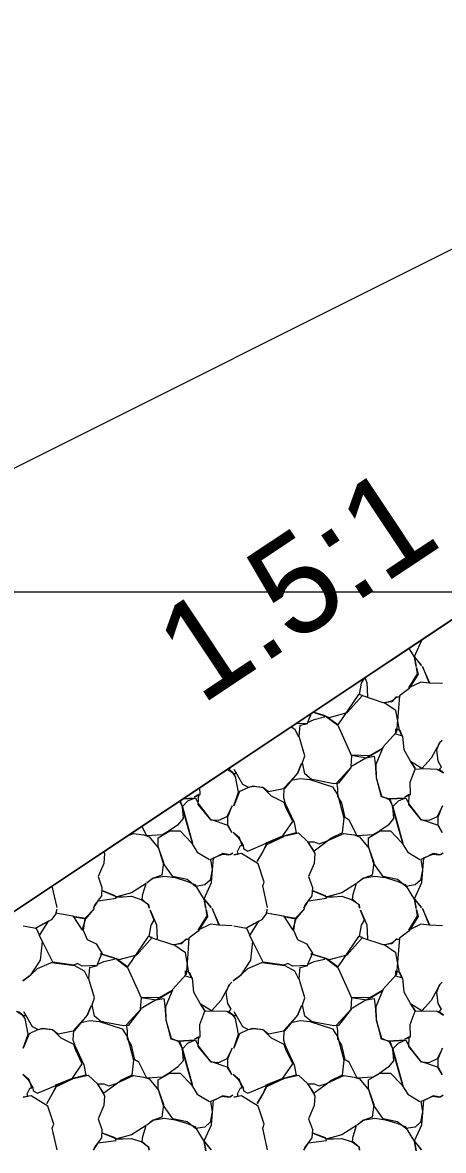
# Model space of a CAD drawing. Extents: x -26 to 2998798, y -429 to 819149.
# Drawn here: x 254.02 to 258.3, y 2527.31 to 2538.79 of the extents above; entities that cross this region are included whole.
import ezdxf

# ---------------------------------------------------------------- set-up
doc = ezdxf.new("R2010")
doc.units = 0
for name, color, linetype in [('DESIGN - EARTHWORK - Shapes', 7, 'Continuous'), ('DESIGN - PROFILE - Patterning', 7, 'Continuous'), ('DESIGN - SCRATCH - User 3', 7, 'Continuous'), ('DESIGN - SCRATCH - User 4', 7, 'Continuous'), ('DESIGN - SHEET - Linework', 7, 'Continuous'), ('DESIGN - TYPICAL - Finished Grade and Subgrade', 7, 'Continuous'), ('DESIGN - TYPICAL - Finished Grade Slopes Text', 7, 'Continuous')]:
    doc.layers.add(name, color=color, linetype=linetype)

msp = doc.modelspace()

# ---------------------------------------------------------------- linework, layer by layer
at = {"layer": 'DESIGN - EARTHWORK - Shapes'}
msp.add_lwpolyline([(309, 2547.734), (300, 2547.914), (299.208, 2547.909), (289, 2547.848), (281.017, 2547.801), (225.777, 2510.974)], dxfattribs=at)
at = {"layer": 'DESIGN - PROFILE - Patterning'}
for p, q in [((281.017, 2547.801), (225.777, 2510.974)), ((254.374, 2529.786), (254.324, 2530.005))]:
    msp.add_line(p, q, dxfattribs=at)
for points in [[(257.952, 2532.424), (258.009, 2532.331), (258.024, 2532.241), (258.009, 2532.336), (258.079, 2532.251), (258.009, 2532.341), (258.084, 2532.506), (258.084, 2532.512)], [(258.294, 2532.066), (258.164, 2532.071), (258.089, 2532.241), (258.159, 2532.071), (258.074, 2532.081), (257.949, 2532.021), (258.039, 2532.166), (258.029, 2532.231), (258.044, 2532.161), (257.949, 2532.011), (257.854, 2531.941), (257.839, 2531.731), (257.824, 2531.571), (257.689, 2531.421), (257.614, 2531.241), (257.619, 2531.106), (257.674, 2530.921), (257.749, 2530.886), (257.789, 2530.811), (257.889, 2530.441), (257.784, 2530.811), (257.844, 2530.871), (257.909, 2530.901), (257.744, 2530.891), (257.919, 2530.901), (257.959, 2530.831), (258.069, 2530.686), (258.249, 2530.626), (258.289, 2530.551), (258.249, 2530.621), (258.249, 2530.711), (258.294, 2530.821), (258.239, 2530.711), (258.154, 2530.671), (258.079, 2530.676), (257.949, 2530.836), (257.954, 2530.936), (257.909, 2530.911), (257.969, 2530.936), (257.964, 2531.061), (258.014, 2531.196), (258.104, 2531.201), (258.239, 2531.196), (258.304, 2531.156), (258.259, 2531.191), (258.284, 2531.216), (258.249, 2531.276), (258.234, 2531.391), (258.264, 2531.466), (258.289, 2531.491), (258.269, 2531.471), (258.219, 2531.381), (258.179, 2531.306), (258.084, 2531.201), (257.969, 2531.271), (258.014, 2531.201), (257.969, 2531.276), (257.904, 2531.391), (257.889, 2531.531), (257.819, 2531.551), (257.819, 2531.606), (257.859, 2531.591), (257.884, 2531.531), (257.854, 2531.591), (257.819, 2531.791), (257.699, 2531.871), (257.779, 2531.891), (257.829, 2531.931), (257.854, 2531.926), (257.819, 2531.926), (257.779, 2531.881), (257.689, 2531.871), (257.484, 2531.941), (257.449, 2531.956), (257.469, 2532.071), (257.499, 2532.121), (257.499, 2532.122)], [(257.503, 2532.124), (257.524, 2532.076), (257.529, 2531.931)], [(256.977, 2531.774), (257.144, 2531.721), (257.324, 2531.771), (257.479, 2531.946), (257.439, 2531.956), (257.229, 2531.646), (257.109, 2531.731), (257.229, 2531.641), (257.329, 2531.416), (257.369, 2531.331), (257.359, 2531.221), (257.514, 2531.311), (257.569, 2531.336), (257.684, 2531.406), (257.554, 2531.331), (257.369, 2531.336), (257.519, 2531.311), (257.599, 2531.326), (257.609, 2531.251), (257.619, 2531.111), (257.669, 2530.916), (257.759, 2530.891), (257.784, 2530.816), (257.794, 2530.691), (257.739, 2530.626), (257.654, 2530.566), (257.584, 2530.526), (257.424, 2530.516), (257.344, 2530.676), (257.304, 2530.701), (257.269, 2530.851), (257.229, 2530.916), (257.229, 2531.001), (257.219, 2531.056), (257.364, 2531.216), (257.234, 2531.051), (257.189, 2531.046), (257.004, 2531.081), (256.959, 2531.091), (256.894, 2531.146), (256.869, 2531.261), (256.894, 2531.331), (256.834, 2531.526), (256.844, 2531.641), (256.924, 2531.661), (256.802, 2531.657)], [(256.958, 2531.761), (256.919, 2531.671), (256.989, 2531.701), (257.094, 2531.726), (257.099, 2531.736), (256.977, 2531.774)], [(256.754, 2531.625), (256.789, 2531.606), (256.829, 2531.526)], [(256.514, 2529.786), (256.464, 2530.006), (256.479, 2530.046), (256.419, 2530.231), (256.249, 2530.336), (256.169, 2530.321), (256.214, 2530.331), (256.209, 2530.356), (256.239, 2530.416), (256.254, 2530.416), (256.229, 2530.496), (256.164, 2530.551), (256.219, 2530.496), (256.264, 2530.416), (256.269, 2530.386), (256.314, 2530.361), (256.499, 2530.441), (256.674, 2530.506), (256.504, 2530.426), (256.464, 2530.356), (256.409, 2530.256), (256.464, 2530.351), (256.499, 2530.426), (256.499, 2530.446), (256.669, 2530.516), (256.769, 2530.661), (256.699, 2530.806), (256.684, 2530.856), (256.554, 2530.921), (256.514, 2530.961), (256.469, 2531.006), (256.364, 2531.021), (256.314, 2531.006), (256.229, 2530.966), (256.169, 2530.821), (256.219, 2530.961), (256.189, 2531.121), (256.164, 2531.151), (256.194, 2531.151), (256.174, 2531.191), (256.259, 2531.041), (256.319, 2531.011), (256.369, 2531.021), (256.464, 2531.011), (256.524, 2530.966), (256.694, 2531.001), (256.819, 2531.151), (256.859, 2531.251), (256.819, 2531.151), (256.739, 2531.066), (256.679, 2531.001), (256.674, 2530.906), (256.694, 2530.846), (256.784, 2530.651), (256.804, 2530.546), (256.674, 2530.511), (256.829, 2530.546), (256.924, 2530.456), (256.994, 2530.336), (256.989, 2530.236), (256.929, 2530.101), (256.969, 2529.991), (256.964, 2529.906), (256.894, 2529.811), (256.884, 2529.781), (256.929, 2529.856), (257.114, 2529.881), (257.104, 2529.906), (256.974, 2529.956), (257.119, 2529.896), (257.184, 2529.896), (257.269, 2529.901), (257.374, 2529.866), (257.444, 2529.816), (257.449, 2529.781), (257.444, 2529.811), (257.379, 2529.871), (257.384, 2529.921), (257.419, 2530.031), (257.269, 2529.936), (257.119, 2529.896)], [(256.105, 2531.192), (256.164, 2531.156), (256.119, 2531.191), (256.144, 2531.216), (256.143, 2531.218)], [(255.658, 2530.894), (255.779, 2530.901), (255.819, 2530.831), (255.929, 2530.686), (256.109, 2530.626), (256.149, 2530.551), (256.109, 2530.621), (256.109, 2530.711), (256.154, 2530.821), (256.099, 2530.711), (256.014, 2530.671), (255.939, 2530.676), (255.809, 2530.836), (255.814, 2530.936), (255.769, 2530.911), (255.829, 2530.936), (255.826, 2531.007)], [(256.754, 2531.081), (256.844, 2531.101), (256.944, 2531.091), (257.174, 2531.016), (257.229, 2530.931), (257.289, 2530.696), (257.274, 2530.546), (257.159, 2530.491), (257.124, 2530.461), (256.989, 2530.361), (256.924, 2530.456), (256.989, 2530.456), (257.039, 2530.436), (257.114, 2530.461), (257.289, 2530.541), (257.394, 2530.526), (257.449, 2530.506), (257.544, 2530.391), (257.594, 2530.246), (257.579, 2530.116), (257.494, 2530.086), (257.424, 2530.036), (257.484, 2530.086), (257.604, 2530.106), (257.714, 2530.091), (257.829, 2530.056), (257.914, 2530.021), (258.009, 2529.866), (258.024, 2529.776), (258.009, 2529.871), (258.079, 2529.786), (258.009, 2529.876), (258.084, 2530.041), (258.104, 2530.291), (258.194, 2530.331), (258.259, 2530.321), (258.299, 2530.341), (258.274, 2530.321), (258.199, 2530.336), (258.114, 2530.291), (258.074, 2530.276), (258.089, 2530.171), (258.069, 2530.066), (258.014, 2530.016), (257.919, 2530.001), (257.834, 2530.071), (257.689, 2530.101), (257.594, 2530.236), (257.539, 2530.406), (257.539, 2530.496), (257.659, 2530.566), (257.764, 2530.566), (257.879, 2530.446), (257.939, 2530.351), (258.064, 2530.276)], [(255.618, 2530.868), (255.649, 2530.811), (255.749, 2530.441), (255.644, 2530.811), (255.704, 2530.871), (255.769, 2530.901), (255.658, 2530.894)], [(255.625, 2530.873), (255.644, 2530.816), (255.654, 2530.691), (255.599, 2530.626), (255.514, 2530.566), (255.444, 2530.526), (255.284, 2530.516), (255.235, 2530.613)], [(255.082, 2530.511), (255.149, 2530.541), (255.254, 2530.526), (255.309, 2530.506), (255.404, 2530.391), (255.454, 2530.246), (255.439, 2530.116), (255.354, 2530.086), (255.284, 2530.036), (255.344, 2530.086), (255.464, 2530.106), (255.574, 2530.091), (255.689, 2530.056), (255.774, 2530.021), (255.869, 2529.866), (255.884, 2529.776), (255.869, 2529.871), (255.939, 2529.786), (255.869, 2529.876), (255.944, 2530.041), (255.964, 2530.291), (256.054, 2530.331), (256.119, 2530.321), (256.159, 2530.341), (256.134, 2530.321), (256.059, 2530.336), (255.974, 2530.291), (255.934, 2530.276), (255.949, 2530.171), (255.929, 2530.066), (255.874, 2530.016), (255.779, 2530.001), (255.694, 2530.071), (255.549, 2530.101), (255.454, 2530.236), (255.399, 2530.406), (255.399, 2530.496), (255.519, 2530.566), (255.624, 2530.566), (255.739, 2530.446), (255.799, 2530.351), (255.924, 2530.276)], [(254.844, 2530.352), (254.854, 2530.336), (254.849, 2530.236), (254.789, 2530.101), (254.829, 2529.991), (254.824, 2529.906), (254.754, 2529.811), (254.744, 2529.781), (254.789, 2529.856), (254.974, 2529.881), (254.964, 2529.906), (254.834, 2529.956), (254.979, 2529.896), (255.044, 2529.896), (255.129, 2529.901), (255.234, 2529.866), (255.304, 2529.816), (255.309, 2529.781), (255.304, 2529.811), (255.239, 2529.871), (255.244, 2529.921), (255.279, 2530.031), (255.129, 2529.936), (254.979, 2529.896)], [(254.029, 2529.601), (254.159, 2529.576), (254.194, 2529.501), (254.284, 2529.646), (254.154, 2529.576), (254.319, 2529.666), (254.364, 2529.721), (254.369, 2529.766), (254.359, 2529.731), (254.534, 2529.701), (254.629, 2529.556), (254.664, 2529.676), (254.534, 2529.696), (254.664, 2529.671), (254.754, 2529.776), (254.654, 2529.676), (254.639, 2529.556), (254.679, 2529.461), (254.769, 2529.416), (254.829, 2529.321), (254.779, 2529.206), (254.849, 2529.236), (254.954, 2529.261), (254.959, 2529.271), (254.814, 2529.316), (255.004, 2529.256), (255.184, 2529.306), (255.339, 2529.481), (255.299, 2529.491), (255.089, 2529.181), (254.969, 2529.266), (255.089, 2529.176), (255.189, 2528.951), (255.229, 2528.866), (255.219, 2528.756), (255.374, 2528.846), (255.429, 2528.871), (255.544, 2528.941), (255.414, 2528.866), (255.229, 2528.871), (255.379, 2528.846), (255.459, 2528.861), (255.469, 2528.786), (255.479, 2528.646), (255.529, 2528.451), (255.619, 2528.426), (255.644, 2528.351), (255.654, 2528.226), (255.599, 2528.161), (255.514, 2528.101), (255.444, 2528.061), (255.284, 2528.051), (255.204, 2528.211), (255.164, 2528.236), (255.129, 2528.386), (255.089, 2528.451), (255.089, 2528.536), (255.079, 2528.591), (255.224, 2528.751), (255.094, 2528.586), (255.049, 2528.581), (254.864, 2528.616), (254.819, 2528.626), (254.754, 2528.681), (254.729, 2528.796), (254.754, 2528.866), (254.694, 2529.061), (254.704, 2529.176), (254.784, 2529.196), (254.629, 2529.191), (254.579, 2529.216), (254.544, 2529.201), (254.329, 2529.231), (254.219, 2529.446), (254.189, 2529.506), (254.219, 2529.441), (254.199, 2529.251), (254.099, 2529.096), (254.024, 2529.041), (254.104, 2529.101), (254.174, 2529.166), (254.314, 2529.226), (254.549, 2529.196), (254.649, 2529.141), (254.689, 2529.061)], [(256.154, 2529.601), (256.024, 2529.606), (255.949, 2529.776), (256.019, 2529.606), (255.934, 2529.616), (255.809, 2529.556), (255.899, 2529.701), (255.889, 2529.766), (255.904, 2529.696), (255.809, 2529.546), (255.714, 2529.476), (255.699, 2529.266), (255.684, 2529.106), (255.549, 2528.956), (255.474, 2528.776), (255.479, 2528.641), (255.534, 2528.456), (255.609, 2528.421), (255.649, 2528.346), (255.749, 2527.976), (255.644, 2528.346), (255.704, 2528.406), (255.769, 2528.436), (255.604, 2528.426), (255.779, 2528.436), (255.819, 2528.366), (255.929, 2528.221), (256.109, 2528.161), (256.149, 2528.086), (256.109, 2528.156), (256.109, 2528.246), (256.154, 2528.356), (256.099, 2528.246), (256.014, 2528.206), (255.939, 2528.211), (255.809, 2528.371), (255.814, 2528.471), (255.769, 2528.446), (255.829, 2528.471), (255.824, 2528.596), (255.874, 2528.731), (255.964, 2528.736), (256.099, 2528.731), (256.164, 2528.691), (256.119, 2528.726), (256.144, 2528.751), (256.109, 2528.811), (256.094, 2528.926), (256.124, 2529.001), (256.149, 2529.026), (256.129, 2529.006), (256.079, 2528.916), (256.039, 2528.841), (255.944, 2528.736), (255.829, 2528.806), (255.874, 2528.736), (255.829, 2528.811), (255.764, 2528.926), (255.749, 2529.066), (255.679, 2529.086), (255.679, 2529.141), (255.719, 2529.126), (255.744, 2529.066), (255.714, 2529.126), (255.679, 2529.326), (255.559, 2529.406), (255.639, 2529.426), (255.689, 2529.466), (255.714, 2529.461), (255.679, 2529.461), (255.639, 2529.416), (255.549, 2529.406), (255.344, 2529.476), (255.309, 2529.491), (255.329, 2529.606), (255.359, 2529.656), (255.319, 2529.761), (255.384, 2529.611), (255.389, 2529.466)], [(256.169, 2529.601), (256.299, 2529.576), (256.334, 2529.501), (256.424, 2529.646), (256.294, 2529.576), (256.459, 2529.666), (256.504, 2529.721), (256.509, 2529.766), (256.499, 2529.731), (256.674, 2529.701), (256.769, 2529.556), (256.804, 2529.676), (256.674, 2529.696), (256.804, 2529.671), (256.894, 2529.776), (256.794, 2529.676), (256.779, 2529.556), (256.819, 2529.461), (256.909, 2529.416), (256.969, 2529.321), (256.919, 2529.206), (256.989, 2529.236), (257.094, 2529.261), (257.099, 2529.271), (256.954, 2529.316), (257.144, 2529.256), (257.324, 2529.306), (257.479, 2529.481), (257.439, 2529.491), (257.229, 2529.181), (257.109, 2529.266), (257.229, 2529.176), (257.329, 2528.951), (257.369, 2528.866), (257.359, 2528.756), (257.514, 2528.846), (257.569, 2528.871), (257.684, 2528.941), (257.554, 2528.866), (257.369, 2528.871), (257.519, 2528.846), (257.599, 2528.861), (257.609, 2528.786), (257.619, 2528.646), (257.669, 2528.451), (257.759, 2528.426), (257.784, 2528.351), (257.794, 2528.226), (257.739, 2528.161), (257.654, 2528.101), (257.584, 2528.061), (257.424, 2528.051), (257.344, 2528.211), (257.304, 2528.236), (257.269, 2528.386), (257.229, 2528.451), (257.229, 2528.536), (257.219, 2528.591), (257.364, 2528.751), (257.234, 2528.586), (257.189, 2528.581), (257.004, 2528.616), (256.959, 2528.626), (256.894, 2528.681), (256.869, 2528.796), (256.894, 2528.866), (256.834, 2529.061), (256.844, 2529.176), (256.924, 2529.196), (256.769, 2529.191), (256.719, 2529.216), (256.684, 2529.201), (256.469, 2529.231), (256.359, 2529.446), (256.329, 2529.506), (256.359, 2529.441), (256.339, 2529.251), (256.239, 2529.096), (256.164, 2529.041), (256.244, 2529.101), (256.314, 2529.166), (256.454, 2529.226), (256.689, 2529.196), (256.789, 2529.141), (256.829, 2529.061)], [(258.294, 2529.601), (258.164, 2529.606), (258.089, 2529.776), (258.159, 2529.606), (258.074, 2529.616), (257.949, 2529.556), (258.039, 2529.701), (258.029, 2529.766), (258.044, 2529.696), (257.949, 2529.546), (257.854, 2529.476), (257.839, 2529.266), (257.824, 2529.106), (257.689, 2528.956), (257.614, 2528.776), (257.619, 2528.641), (257.674, 2528.456), (257.749, 2528.421), (257.789, 2528.346), (257.889, 2527.976), (257.784, 2528.346), (257.844, 2528.406), (257.909, 2528.436), (257.744, 2528.426), (257.919, 2528.436), (257.959, 2528.366), (258.069, 2528.221), (258.249, 2528.161), (258.289, 2528.086), (258.249, 2528.156), (258.249, 2528.246), (258.294, 2528.356), (258.239, 2528.246), (258.154, 2528.206), (258.079, 2528.211), (257.949, 2528.371), (257.954, 2528.471), (257.909, 2528.446), (257.969, 2528.471), (257.964, 2528.596), (258.014, 2528.731), (258.104, 2528.736), (258.239, 2528.731), (258.304, 2528.691), (258.259, 2528.726), (258.284, 2528.751), (258.249, 2528.811), (258.234, 2528.926), (258.264, 2529.001), (258.289, 2529.026), (258.269, 2529.006), (258.219, 2528.916), (258.179, 2528.841), (258.084, 2528.736), (257.969, 2528.806), (258.014, 2528.736), (257.969, 2528.811), (257.904, 2528.926), (257.889, 2529.066), (257.819, 2529.086), (257.819, 2529.141), (257.859, 2529.126), (257.884, 2529.066), (257.854, 2529.126), (257.819, 2529.326), (257.699, 2529.406), (257.779, 2529.426), (257.829, 2529.466), (257.854, 2529.461), (257.819, 2529.461), (257.779, 2529.416), (257.689, 2529.406), (257.484, 2529.476), (257.449, 2529.491), (257.469, 2529.606), (257.499, 2529.656), (257.459, 2529.761), (257.524, 2529.611), (257.529, 2529.466)], [(253.959, 2528.731), (254.024, 2528.691), (253.979, 2528.726)], [(254.374, 2527.321), (254.324, 2527.541), (254.339, 2527.581), (254.279, 2527.766), (254.109, 2527.871), (254.029, 2527.856), (254.074, 2527.866), (254.069, 2527.891), (254.099, 2527.951), (254.114, 2527.951), (254.089, 2528.031), (254.024, 2528.086), (254.079, 2528.031), (254.124, 2527.951), (254.129, 2527.921), (254.174, 2527.896), (254.359, 2527.976), (254.534, 2528.041), (254.364, 2527.961), (254.324, 2527.891), (254.269, 2527.791), (254.324, 2527.886), (254.359, 2527.961), (254.359, 2527.981), (254.529, 2528.051), (254.629, 2528.196), (254.559, 2528.341), (254.544, 2528.391), (254.414, 2528.456), (254.374, 2528.496), (254.329, 2528.541), (254.224, 2528.556), (254.174, 2528.541), (254.089, 2528.501), (254.029, 2528.356), (254.079, 2528.496), (254.049, 2528.656), (254.024, 2528.686), (254.054, 2528.686), (254.034, 2528.726), (254.119, 2528.576), (254.179, 2528.546), (254.229, 2528.556), (254.324, 2528.546), (254.384, 2528.501), (254.554, 2528.536), (254.679, 2528.686), (254.719, 2528.786), (254.679, 2528.686), (254.599, 2528.601), (254.539, 2528.536), (254.534, 2528.441), (254.554, 2528.381), (254.644, 2528.186), (254.664, 2528.081), (254.534, 2528.046), (254.689, 2528.081), (254.784, 2527.991), (254.854, 2527.871), (254.849, 2527.771), (254.789, 2527.636), (254.829, 2527.526), (254.824, 2527.441), (254.754, 2527.346), (254.744, 2527.316), (254.789, 2527.391), (254.974, 2527.416), (254.964, 2527.441), (254.834, 2527.491), (254.979, 2527.431), (255.044, 2527.431), (255.129, 2527.436), (255.234, 2527.401), (255.304, 2527.351), (255.309, 2527.316), (255.304, 2527.346), (255.239, 2527.406), (255.244, 2527.456), (255.279, 2527.566), (255.129, 2527.471), (254.979, 2527.431)], [(256.514, 2527.321), (256.464, 2527.541), (256.479, 2527.581), (256.419, 2527.766), (256.249, 2527.871), (256.169, 2527.856), (256.214, 2527.866), (256.209, 2527.891), (256.239, 2527.951), (256.254, 2527.951), (256.229, 2528.031), (256.164, 2528.086), (256.219, 2528.031), (256.264, 2527.951), (256.269, 2527.921), (256.314, 2527.896), (256.499, 2527.976), (256.674, 2528.041), (256.504, 2527.961), (256.464, 2527.891), (256.409, 2527.791), (256.464, 2527.886), (256.499, 2527.961), (256.499, 2527.981), (256.669, 2528.051), (256.769, 2528.196), (256.699, 2528.341), (256.684, 2528.391), (256.554, 2528.456), (256.514, 2528.496), (256.469, 2528.541), (256.364, 2528.556), (256.314, 2528.541), (256.229, 2528.501), (256.169, 2528.356), (256.219, 2528.496), (256.189, 2528.656), (256.164, 2528.686), (256.194, 2528.686), (256.174, 2528.726), (256.259, 2528.576), (256.319, 2528.546), (256.369, 2528.556), (256.464, 2528.546), (256.524, 2528.501), (256.694, 2528.536), (256.819, 2528.686), (256.859, 2528.786), (256.819, 2528.686), (256.739, 2528.601), (256.679, 2528.536), (256.674, 2528.441), (256.694, 2528.381), (256.784, 2528.186), (256.804, 2528.081), (256.674, 2528.046), (256.829, 2528.081), (256.924, 2527.991), (256.994, 2527.871), (256.989, 2527.771), (256.929, 2527.636), (256.969, 2527.526), (256.964, 2527.441), (256.894, 2527.346), (256.884, 2527.316), (256.929, 2527.391), (257.114, 2527.416), (257.104, 2527.441), (256.974, 2527.491), (257.119, 2527.431), (257.184, 2527.431), (257.269, 2527.436), (257.374, 2527.401), (257.444, 2527.351), (257.449, 2527.316), (257.444, 2527.346), (257.379, 2527.406), (257.384, 2527.456), (257.419, 2527.566), (257.269, 2527.471), (257.119, 2527.431)], [(254.614, 2528.616), (254.704, 2528.636), (254.804, 2528.626), (255.034, 2528.551), (255.089, 2528.466), (255.149, 2528.231), (255.134, 2528.081), (255.019, 2528.026), (254.984, 2527.996), (254.849, 2527.896), (254.784, 2527.991), (254.849, 2527.991), (254.899, 2527.971), (254.974, 2527.996), (255.149, 2528.076), (255.254, 2528.061), (255.309, 2528.041), (255.404, 2527.926), (255.454, 2527.781), (255.439, 2527.651), (255.354, 2527.621), (255.284, 2527.571), (255.344, 2527.621), (255.464, 2527.641), (255.574, 2527.626), (255.689, 2527.591), (255.774, 2527.556), (255.869, 2527.401), (255.884, 2527.311), (255.869, 2527.406), (255.939, 2527.321), (255.869, 2527.411), (255.944, 2527.576), (255.964, 2527.826), (256.054, 2527.866), (256.119, 2527.856), (256.159, 2527.876), (256.134, 2527.856), (256.059, 2527.871), (255.974, 2527.826), (255.934, 2527.811), (255.949, 2527.706), (255.929, 2527.601), (255.874, 2527.551), (255.779, 2527.536), (255.694, 2527.606), (255.549, 2527.636), (255.454, 2527.771), (255.399, 2527.941), (255.399, 2528.031), (255.519, 2528.101), (255.624, 2528.101), (255.739, 2527.981), (255.799, 2527.886), (255.924, 2527.811)], [(256.754, 2528.616), (256.844, 2528.636), (256.944, 2528.626), (257.174, 2528.551), (257.229, 2528.466), (257.289, 2528.231), (257.274, 2528.081), (257.159, 2528.026), (257.124, 2527.996), (256.989, 2527.896), (256.924, 2527.991), (256.989, 2527.991), (257.039, 2527.971), (257.114, 2527.996), (257.289, 2528.076), (257.394, 2528.061), (257.449, 2528.041), (257.544, 2527.926), (257.594, 2527.781), (257.579, 2527.651), (257.494, 2527.621), (257.424, 2527.571), (257.484, 2527.621), (257.604, 2527.641), (257.714, 2527.626), (257.829, 2527.591), (257.914, 2527.556), (258.009, 2527.401), (258.024, 2527.311), (258.009, 2527.406), (258.079, 2527.321), (258.009, 2527.411), (258.084, 2527.576), (258.104, 2527.826), (258.194, 2527.866), (258.259, 2527.856), (258.299, 2527.876), (258.274, 2527.856), (258.199, 2527.871), (258.114, 2527.826), (258.074, 2527.811), (258.089, 2527.706), (258.069, 2527.601), (258.014, 2527.551), (257.919, 2527.536), (257.834, 2527.606), (257.689, 2527.636), (257.594, 2527.771), (257.539, 2527.941), (257.539, 2528.031), (257.659, 2528.101), (257.764, 2528.101), (257.879, 2527.981), (257.939, 2527.886), (258.064, 2527.811)]]:
    msp.add_lwpolyline(points, dxfattribs=at)
at = {"layer": 'DESIGN - SCRATCH - User 3'}
msp.add_lwpolyline([(299.208, 2547.909), (289, 2547.848), (281.017, 2547.801), (225.777, 2510.974), (230.186, 2511.075), (242.134, 2511.654), (249.866, 2511.679), (265.88, 2511.997), (267.637, 2514.832), (268.915, 2514.926), (272.672, 2515.326), (273.716, 2515.78), (276.491, 2517.642), (280.232, 2519.336), (286.77, 2522.859), (291.559, 2525.363), (293.354, 2526.226), (296.534, 2527.058), (268.06, 2527.144)], close=True, dxfattribs=at)
at = {"layer": 'DESIGN - SCRATCH - User 4'}
msp.add_line((281.017, 2547.801), (220.5, 2517.542), dxfattribs=at)
at = {"layer": 'DESIGN - SHEET - Linework'}
msp.add_line((150, 2533), (450, 2533), dxfattribs=at)
at = {"layer": 'DESIGN - TYPICAL - Finished Grade and Subgrade'}
msp.add_line((281.017, 2547.801), (225.777, 2510.974), dxfattribs=at)

# ---------------------------------------------------------------- texts
at = {"layer": 'DESIGN - TYPICAL - Finished Grade Slopes Text'}
msp.add_text('1.5:1', height=1, rotation=33.5963, dxfattribs=at).set_placement((255.834, 2531.839))

doc.saveas('drawing.dxf')
